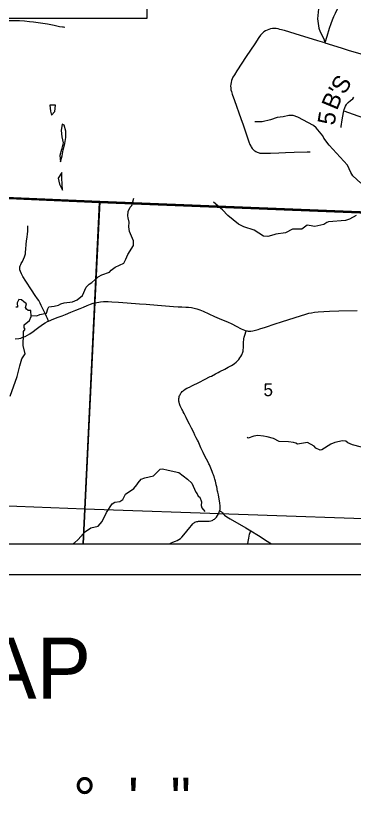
# Model space of a CAD drawing. Extents: x 0 to 34, y 0 to 22.
# Drawn here: x 6.203 to 7.308, y 13.194 to 15.827 of the extents above; entities that cross this region are included whole.
import ezdxf

# ---------------------------------------------------------------- set-up
doc = ezdxf.new("R2010")
doc.units = 0
for name, color, linetype in [('Default', 7, 'Continuous'), ('GM_X_County_Road', 7, 'Continuous'), ('GM_X_County_Road_Text', 7, 'Continuous'), ('GM_X_Minor_Lake', 7, 'Continuous'), ('GM_X_Minor_River', 7, 'Continuous'), ('GM_X_Rail_Line', 7, 'Continuous'), ('GM_X_Section', 7, 'Continuous'), ('GM_X_Section_Text', 7, 'Continuous'), ('GM_X_Township_Road', 7, 'Continuous'), ('GM_X_Unincorporated_Text', 7, 'Continuous'), ('SH_Data', 7, 'Continuous'), ('SH_Text', 7, 'Continuous')]:
    doc.layers.add(name, color=color, linetype=linetype)

msp = doc.modelspace()

# ---------------------------------------------------------------- linework, layer by layer
at = {"layer": 'Default'}
msp.add_lwpolyline([(5.112, 16.1987), (6.6303, 16.1987), (6.6303, 15.8189), (5.112, 15.8189)], close=True, dxfattribs=at)
at = {"layer": 'GM_X_County_Road'}
msp.add_line((7.2752, 15.5169), (7.3927, 15.4747), dxfattribs=at)
for points in [[(7.3114, 16.0367), (7.2988, 15.9951), (7.2916, 15.9713), (7.2816, 15.9386), (7.26, 15.8672), (7.2569, 15.8583), (7.2534, 15.8497), (7.2468, 15.8356), (7.2415, 15.8243), (7.2365, 15.813), (7.2321, 15.8014), (7.2272, 15.7867), (7.2191, 15.76), (7.2128, 15.7391)], [(7.2128, 15.7391), (7.1905, 15.7457), (7.1163, 15.7682), (7.0807, 15.7791), (7.0658, 15.7834), (7.0598, 15.7848), (7.0538, 15.7857), (7.0477, 15.7861), (7.0416, 15.7859), (7.0356, 15.7849), (7.0297, 15.7833), (7.024, 15.781), (7.0186, 15.7782), (7.0135, 15.7749), (7.0111, 15.773), (7.0067, 15.7688), (7.0027, 15.7642), (6.9972, 15.7568), (6.9834, 15.7362), (6.9561, 15.6947), (6.9251, 15.6482), (6.9169, 15.6351), (6.9123, 15.6271), (6.9097, 15.6215), (6.9075, 15.6158), (6.906, 15.6099), (6.905, 15.6039), (6.9047, 15.5978), (6.905, 15.5917), (6.9058, 15.5856), (6.9072, 15.5797), (6.9099, 15.5708), (6.9171, 15.5504), (6.9378, 15.4919), (6.9452, 15.4715), (6.9536, 15.4481), (6.9648, 15.4159), (6.9681, 15.4072), (6.9707, 15.4016), (6.9721, 15.3989), (6.9755, 15.3939), (6.9774, 15.3915), (6.9795, 15.3893), (6.9818, 15.3873), (6.9842, 15.3855), (6.9867, 15.3838), (6.9893, 15.3823), (6.9921, 15.3811), (6.9949, 15.38), (6.9978, 15.3793), (7.0008, 15.3787), (7.0069, 15.3783), (7.0347, 15.3788), (7.0626, 15.3799), (7.0843, 15.3807), (7.1122, 15.3817), (7.1555, 15.3827), (7.1648, 15.3831)], [(7.2128, 15.7391), (7.2661, 15.7227), (7.293, 15.7146), (7.3349, 15.7022), (7.3438, 15.6992), (7.3467, 15.698), (7.3496, 15.6965), (7.3525, 15.6944)], [(7.2662, 15.4625), (7.2666, 15.4656), (7.2698, 15.4872), (7.274, 15.5117), (7.2752, 15.5169), (7.2761, 15.5208), (7.278, 15.5266), (7.2806, 15.5322), (7.2837, 15.5374), (7.2855, 15.5399), (7.2876, 15.5421), (7.2898, 15.5442), (7.2971, 15.5501), (7.3041, 15.5564), (7.3084, 15.561)], [(6.3088, 14.8289), (6.3264, 14.8359), (6.3401, 14.8416), (6.3534, 14.8464), (6.3645, 14.851), (6.382, 14.8579), (6.3979, 14.8643), (6.4122, 14.8702), (6.4236, 14.8749), (6.4349, 14.8797), (6.4463, 14.8842), (6.455, 14.8872), (6.4609, 14.8889), (6.462, 14.8892)], [(6.462, 14.8892), (6.467, 14.8903), (6.4732, 14.8914), (6.4793, 14.8922), (6.4886, 14.8929), (6.4979, 14.8932), (6.5041, 14.8931), (6.5165, 14.8922), (6.5382, 14.8904), (6.566, 14.8884), (6.6063, 14.8855), (6.6279, 14.8839), (6.665, 14.8811), (6.7175, 14.8772), (6.733, 14.876), (6.7453, 14.8754), (6.7578, 14.875), (6.7671, 14.8744), (6.7764, 14.8733), (6.7856, 14.8715), (6.7946, 14.869), (6.8034, 14.8658), (6.8149, 14.861), (6.8517, 14.8445), (6.8746, 14.8347), (6.8946, 14.8263), (6.9087, 14.8197), (6.9226, 14.8126), (6.939, 14.8038), (6.9445, 14.801), (6.9501, 14.7988), (6.9555, 14.7973)], [(6.9555, 14.7973), (6.959, 14.7966), (6.962, 14.7962), (6.9651, 14.7961), (6.9681, 14.7961), (6.9712, 14.7963), (6.9772, 14.7973), (6.9862, 14.7994), (6.995, 14.802), (7.0007, 14.8039), (7.0184, 14.8094), (7.0509, 14.8196), (7.0716, 14.8263), (7.1158, 14.8407), (7.1335, 14.8465), (7.1513, 14.8521), (7.1603, 14.8545), (7.1695, 14.8563), (7.1787, 14.8577), (7.1911, 14.8591), (7.2097, 14.8603), (7.2283, 14.8612), (7.2593, 14.8625), (7.3183, 14.8641)], [(6.2, 14.7704), (6.212, 14.7717), (6.2183, 14.7734), (6.2247, 14.7759), (6.2326, 14.779), (6.2403, 14.7832), (6.2481, 14.7878), (6.2581, 14.7949), (6.2685, 14.8027), (6.2772, 14.8095), (6.2848, 14.8147), (6.2925, 14.8198), (6.2978, 14.8231), (6.3059, 14.8275), (6.3088, 14.8289)]]:
    msp.add_lwpolyline(points, dxfattribs=at)
at = {"layer": 'GM_X_Minor_Lake'}
for points in [[(6.3321, 15.5356), (6.3128, 15.5356), (6.3151, 15.5158), (6.3188, 15.5022)], [(6.3188, 15.5022), (6.3294, 15.5151), (6.3321, 15.5356), (6.3128, 15.5356), (6.3151, 15.5158), (6.3188, 15.5022)], [(6.3188, 15.5022), (6.3294, 15.5151), (6.3321, 15.5356)], [(6.3537, 15.4737), (6.3503, 15.4525), (6.3525, 15.4323), (6.3567, 15.4122), (6.351, 15.3906), (6.3453, 15.3708), (6.348, 15.35)], [(6.3537, 15.4737), (6.3503, 15.4525), (6.3525, 15.4323), (6.3567, 15.4122), (6.351, 15.3906), (6.3453, 15.3708), (6.348, 15.35), (6.3529, 15.3693), (6.3571, 15.3891), (6.362, 15.4096), (6.365, 15.4301), (6.365, 15.4498), (6.3601, 15.4695), (6.3537, 15.4737)], [(6.348, 15.35), (6.3529, 15.3693), (6.3571, 15.3891), (6.362, 15.4096), (6.365, 15.4301), (6.365, 15.4498), (6.3601, 15.4695), (6.3537, 15.4737)], [(6.3541, 15.2573), (6.3533, 15.2767), (6.3522, 15.2964), (6.3525, 15.3154), (6.3404, 15.2964), (6.345, 15.2767)], [(6.3541, 15.2573), (6.3533, 15.2767), (6.3522, 15.2964), (6.3525, 15.3154), (6.3404, 15.2964), (6.345, 15.2767), (6.3541, 15.2573), (6.3541, 15.2573)], [(6.345, 15.2767), (6.3541, 15.2573), (6.3541, 15.2573)]]:
    msp.add_lwpolyline(points, dxfattribs=at)
at = {"layer": 'GM_X_Minor_River'}
for points in [[(7.1921, 15.85), (7.1885, 15.8181), (7.1939, 15.7874), (7.1981, 15.7752), (7.21, 15.7521), (7.2127, 15.7404)], [(7.3312, 15.28), (7.3046, 15.3045), (7.2981, 15.3155), (7.2874, 15.3394), (7.2273, 15.4044), (7.2101, 15.4274), (7.2063, 15.435), (7.185, 15.4615), (7.1755, 15.469), (7.1243, 15.4965), (7.1099, 15.5017), (7.1004, 15.502), (7.0955, 15.502), (7.0766, 15.4974), (7.057, 15.495), (7.0347, 15.4873), (7.0083, 15.4803), (6.9837, 15.4809)], [(6.2515, 14.8468), (6.2701, 14.8466), (6.2799, 14.8501), (6.3026, 14.8548), (6.3063, 14.8692), (6.3097, 14.8753), (6.3271, 14.8777), (6.3414, 14.8816), (6.3486, 14.885), (6.3595, 14.8889), (6.3875, 14.8925), (6.4022, 14.899), (6.4199, 14.9128), (6.4323, 14.9398), (6.4413, 14.9501), (6.4503, 14.9555), (6.4598, 14.9635), (6.4714, 14.9734), (6.4831, 14.9807), (6.5088, 14.9892), (6.5133, 14.9957), (6.5269, 15.0049), (6.5556, 15.0183), (6.5623, 15.0313), (6.5687, 15.0472), (6.5867, 15.0766), (6.5873, 15.091), (6.5739, 15.1221), (6.572, 15.1369), (6.5723, 15.1521), (6.5699, 15.1669), (6.5688, 15.1729), (6.5698, 15.1878), (6.5758, 15.2022), (6.5815, 15.2068), (6.5885, 15.2315)], [(7.3151, 15.1747), (7.294, 15.1624), (7.2808, 15.1578), (7.2248, 15.1533), (7.2191, 15.1518), (7.2097, 15.1445), (7.1806, 15.1386), (7.1617, 15.1419), (7.1556, 15.1423), (7.1379, 15.1297), (7.1069, 15.1295), (7.0839, 15.1172), (7.0521, 15.1133), (7.0457, 15.1113), (7.0261, 15.1059), (7.0128, 15.107), (6.9821, 15.1266), (6.9476, 15.1374), (6.9302, 15.1456), (6.8956, 15.1747), (6.8785, 15.1925), (6.8492, 15.2181)], [(6.1837, 14.5834), (6.2057, 14.6477), (6.2149, 14.6827), (6.2216, 14.7059), (6.2325, 14.7219), (6.226, 14.7488), (6.2265, 14.7872), (6.2272, 14.7948), (6.2325, 14.8024), (6.2287, 14.8073), (6.2294, 14.8164), (6.2463, 14.8313), (6.2516, 14.8439), (6.2511, 14.8632), (6.2424, 14.8636), (6.2371, 14.8681), (6.2336, 14.8734), (6.237, 14.8856), (6.2275, 14.8916), (6.2199, 14.898), (6.2116, 14.8999), (6.2059, 14.8884), (6.2072, 14.874), (6.2015, 14.874)], [(7.333, 14.4164), (7.3035, 14.4242), (7.2887, 14.431), (7.2822, 14.4359), (7.2709, 14.4373), (7.2459, 14.4322), (7.2323, 14.4265), (7.2033, 14.4077), (7.198, 14.4065), (7.1832, 14.4129), (7.1783, 14.4197), (7.1559, 14.4318), (7.1238, 14.4267), (7.1177, 14.4297), (7.1101, 14.4315), (7.0946, 14.4337), (7.0639, 14.4351), (7.0446, 14.4445), (7.0238, 14.4504), (7.012, 14.4523), (6.9942, 14.4544), (6.9803, 14.4528), (6.9625, 14.4459), (6.9583, 14.4478)], [(6.3885, 14.1), (6.3942, 14.1035), (6.4062, 14.1145), (6.422, 14.1328), (6.4303, 14.1405), (6.4476, 14.1523), (6.4711, 14.1582), (6.4839, 14.173), (6.4985, 14.2023), (6.5168, 14.2313), (6.5263, 14.237), (6.5425, 14.239), (6.552, 14.2455), (6.5606, 14.2623), (6.5885, 14.281), (6.5982, 14.2929), (6.602, 14.2997), (6.6125, 14.3115), (6.6242, 14.3162), (6.6522, 14.3228), (6.6736, 14.3441), (6.682, 14.3453), (6.7005, 14.3409), (6.735, 14.3331), (6.7638, 14.3116), (6.7775, 14.2991), (6.7909, 14.2696), (6.7951, 14.2639), (6.7989, 14.2567), (6.8042, 14.253), (6.8089, 14.2378), (6.8078, 14.226), (6.8108, 14.2184), (6.8207, 14.2056)]]:
    msp.add_lwpolyline(points, dxfattribs=at)
at = {"layer": 'GM_X_Rail_Line'}
msp.add_lwpolyline([(5.4821, 15.8189), (5.479, 15.731), (5.4522, 15.2638), (6.2705, 15.2288), (6.4764, 15.22), (8.4272, 15.1429)], dxfattribs=at)
for points in [[(2.1, 15.4153), (2.1, 14.1), (6.4223, 14.1), (6.4607, 14.8895), (6.4764, 15.22), (6.2705, 15.2288), (5.4522, 15.2638), (5.2458, 15.271), (5.1044, 15.2759), (4.1973, 15.3118), (4.1956, 15.3121), (4.1849, 15.3132), (4.1743, 15.3141), (4.1061, 15.3185), (4.0782, 15.3206), (4.0381, 15.324), (4.0257, 15.3251), (4.0133, 15.3262), (3.973, 15.329), (3.9451, 15.3313), (3.9123, 15.3323)], [(6.4223, 14.1), (8.9, 14.1), (8.9, 15.1329), (8.4272, 15.1429), (6.4764, 15.22), (6.4607, 14.8895)]]:
    msp.add_lwpolyline(points, close=True, dxfattribs=at)
at = {"layer": 'GM_X_Section'}
for points in [[(6.4755, 15.2172), (6.4272, 14.2142), (5.4247, 14.2527), (5.438, 14.5597), (5.4613, 15.2612)], [(7.4655, 15.1779), (7.4338, 14.1789), (6.4272, 14.2142), (6.4755, 15.2172)]]:
    msp.add_lwpolyline(points, close=True, dxfattribs=at)
at = {"layer": 'GM_X_Township_Road'}
for points in [[(6.0265, 15.7958), (6.0466, 15.7984), (6.072, 15.8019), (6.0843, 15.8036), (6.0965, 15.8054), (6.1088, 15.807), (6.1211, 15.808), (6.1303, 15.809), (6.151, 15.8106), (6.1715, 15.8118), (6.1922, 15.8123), (6.2136, 15.8121), (6.23, 15.8111), (6.2465, 15.8096), (6.2599, 15.8077), (6.2905, 15.8036), (6.3057, 15.8011), (6.3269, 15.7969), (6.345, 15.7931), (6.354, 15.7915), (6.3568, 15.7911), (6.3596, 15.7909), (6.3626, 15.7913)], [(6.3088, 14.8289), (6.3054, 14.8379), (6.3027, 14.8437), (6.3002, 14.8491), (6.2967, 14.8562), (6.2912, 14.8667), (6.2849, 14.8796), (6.2818, 14.8872), (6.279, 14.8921), (6.2768, 14.8964), (6.2726, 14.9023), (6.2656, 14.9123), (6.2529, 14.9311), (6.2349, 14.9595), (6.2249, 14.9746), (6.2201, 14.9834), (6.2169, 14.9911), (6.2151, 14.9962), (6.2148, 14.9994), (6.2148, 15.0032), (6.2154, 15.0063), (6.2162, 15.0095), (6.2178, 15.0137), (6.2197, 15.0178), (6.2233, 15.0244), (6.227, 15.032), (6.23, 15.0392), (6.2322, 15.0454), (6.2333, 15.0495), (6.2339, 15.0542), (6.2346, 15.0641), (6.2358, 15.0795), (6.2371, 15.0916), (6.2387, 15.1038), (6.2399, 15.1139), (6.2406, 15.1217), (6.2408, 15.1311), (6.2408, 15.1409)], [(6.8688, 14.2084), (6.8693, 14.2098), (6.8701, 14.2128), (6.8705, 14.2158), (6.8707, 14.2188), (6.8708, 14.2217), (6.8706, 14.2249), (6.8694, 14.2335), (6.8647, 14.2603), (6.8629, 14.2689), (6.8622, 14.2725), (6.861, 14.2781), (6.8602, 14.2815), (6.8591, 14.2872), (6.8576, 14.2929), (6.857, 14.2956), (6.8564, 14.2982), (6.8559, 14.3007), (6.8554, 14.303), (6.8549, 14.3051), (6.853, 14.3123), (6.8518, 14.3163), (6.8511, 14.3184), (6.8503, 14.3207), (6.8496, 14.3231), (6.8487, 14.3256), (6.8478, 14.3282), (6.8469, 14.3309), (6.8459, 14.3337), (6.8448, 14.3365), (6.8426, 14.3421), (6.8401, 14.3478), (6.8375, 14.3534), (6.8353, 14.3588), (6.8336, 14.3623), (6.8299, 14.3692), (6.8215, 14.385), (6.8153, 14.3987), (6.8075, 14.4146), (6.8026, 14.4257), (6.8004, 14.4312), (6.7993, 14.4341), (6.7967, 14.4392), (6.7923, 14.4472), (6.788, 14.4562), (6.7841, 14.4646), (6.7769, 14.4783), (6.7702, 14.492), (6.7663, 14.4996), (6.7596, 14.5133), (6.7525, 14.5268), (6.7497, 14.5323), (6.7467, 14.5376), (6.7454, 14.5409), (6.7398, 14.5521), (6.7376, 14.5579), (6.7359, 14.5639), (6.7354, 14.5669), (6.7351, 14.57), (6.7351, 14.5731), (6.7354, 14.5762), (6.7359, 14.5792), (6.7367, 14.5822), (6.7378, 14.5851), (6.7391, 14.588), (6.7406, 14.5907), (6.7423, 14.5933), (6.7441, 14.5958), (6.7462, 14.5981), (6.7484, 14.6002), (6.7508, 14.6022), (6.7559, 14.6059), (6.7612, 14.609), (6.7696, 14.6131), (6.7779, 14.6172), (6.803, 14.6297), (6.8196, 14.6382), (6.8381, 14.6477), (6.8416, 14.6492), (6.8551, 14.6563), (6.8636, 14.6606), (6.8692, 14.6636), (6.8854, 14.6721), (6.8965, 14.678), (6.9073, 14.6839), (6.9127, 14.687), (6.9177, 14.6907), (6.9227, 14.6945), (6.9272, 14.6988), (6.9315, 14.7036), (6.9353, 14.7083), (6.9385, 14.7133), (6.9416, 14.7189), (6.9429, 14.7216), (6.9441, 14.7244), (6.945, 14.7274), (6.9456, 14.7304), (6.946, 14.7335), (6.9465, 14.7428), (6.9466, 14.7521), (6.9469, 14.7614), (6.9475, 14.7676), (6.948, 14.7706), (6.9494, 14.7769), (6.9513, 14.7825), (6.9555, 14.7973)], [(6.7012, 14.1), (6.7068, 14.1019), (6.7096, 14.1031), (6.7156, 14.1052), (6.724, 14.109), (6.7298, 14.1117), (6.7351, 14.1144), (6.7406, 14.1182), (6.7451, 14.1223), (6.7513, 14.1292), (6.7609, 14.1416), (6.7712, 14.1532), (6.7771, 14.1604), (6.7809, 14.1653), (6.7828, 14.1676), (6.7851, 14.1695), (6.788, 14.171), (6.7909, 14.1721), (6.7938, 14.1731), (6.7969, 14.1738), (6.7999, 14.1743), (6.8057, 14.1748), (6.8124, 14.1749), (6.8342, 14.1749), (6.8403, 14.1756), (6.8438, 14.1766), (6.8466, 14.1777), (6.849, 14.1794), (6.8516, 14.1811), (6.8539, 14.1831), (6.8561, 14.1854), (6.858, 14.1878), (6.8615, 14.1929), (6.8645, 14.1983), (6.8671, 14.2039), (6.8688, 14.2084)], [(6.8688, 14.2084), (6.8743, 14.2045), (6.8781, 14.2014), (6.8819, 14.1977), (6.8852, 14.1946), (6.8924, 14.1887), (6.9032, 14.1824), (6.955, 14.1523), (6.9707, 14.1427)], [(6.9608, 14.1), (6.962, 14.1084), (6.964, 14.1191), (6.9654, 14.1256), (6.9668, 14.132), (6.9707, 14.1427)], [(6.9707, 14.1427), (6.996, 14.1275), (7.0248, 14.1086), (7.0388, 14.1)]]:
    msp.add_lwpolyline(points, dxfattribs=at)
at = {"layer": 'GM_X_Unincorporated_Text'}
for points in [[(5.4179, 14.1), (6.4225, 14.1), (6.4272, 14.2142), (5.4247, 14.2527)], [(6.4225, 14.1), (7.431, 14.1), (7.4338, 14.1789), (6.4272, 14.2142)]]:
    msp.add_lwpolyline(points, close=True, dxfattribs=at)
at = {"layer": 'SH_Data'}
for p, q in [((2.1, 14.1), (8.9, 14.1)), ((2, 14), (9, 14))]:
    msp.add_line(p, q, dxfattribs=at)

# ---------------------------------------------------------------- texts
at = {"layer": 'GM_X_County_Road_Text'}
for s, rotation, p in [('S', 56.5445, (7.276, 15.567)), ("'", 56.7342, (7.2692, 15.5566)), ('B', 67.3723, (7.2525, 15.5159)), ('5', 80.6061, (7.2445, 15.4675))]:
    msp.add_text(s, height=0.0568, rotation=rotation, dxfattribs=at).set_placement(p)
at = {"layer": 'GM_X_Section_Text'}
msp.add_text('5', height=0.0419, rotation=0, dxfattribs=at).set_placement((7.0121, 14.5834))
at = {"layer": 'SH_Text'}
for s, height, p in [('LOCATION MAP', 0.2, (4.4269, 13.5937)), ('LATITUDE:  39°  \'  "     LONGITUDE:     °  \'  "', 0.14, (3.071, 13.1958))]:
    msp.add_text(s, height=height, dxfattribs=at).set_placement(p)

doc.saveas('drawing.dxf')
